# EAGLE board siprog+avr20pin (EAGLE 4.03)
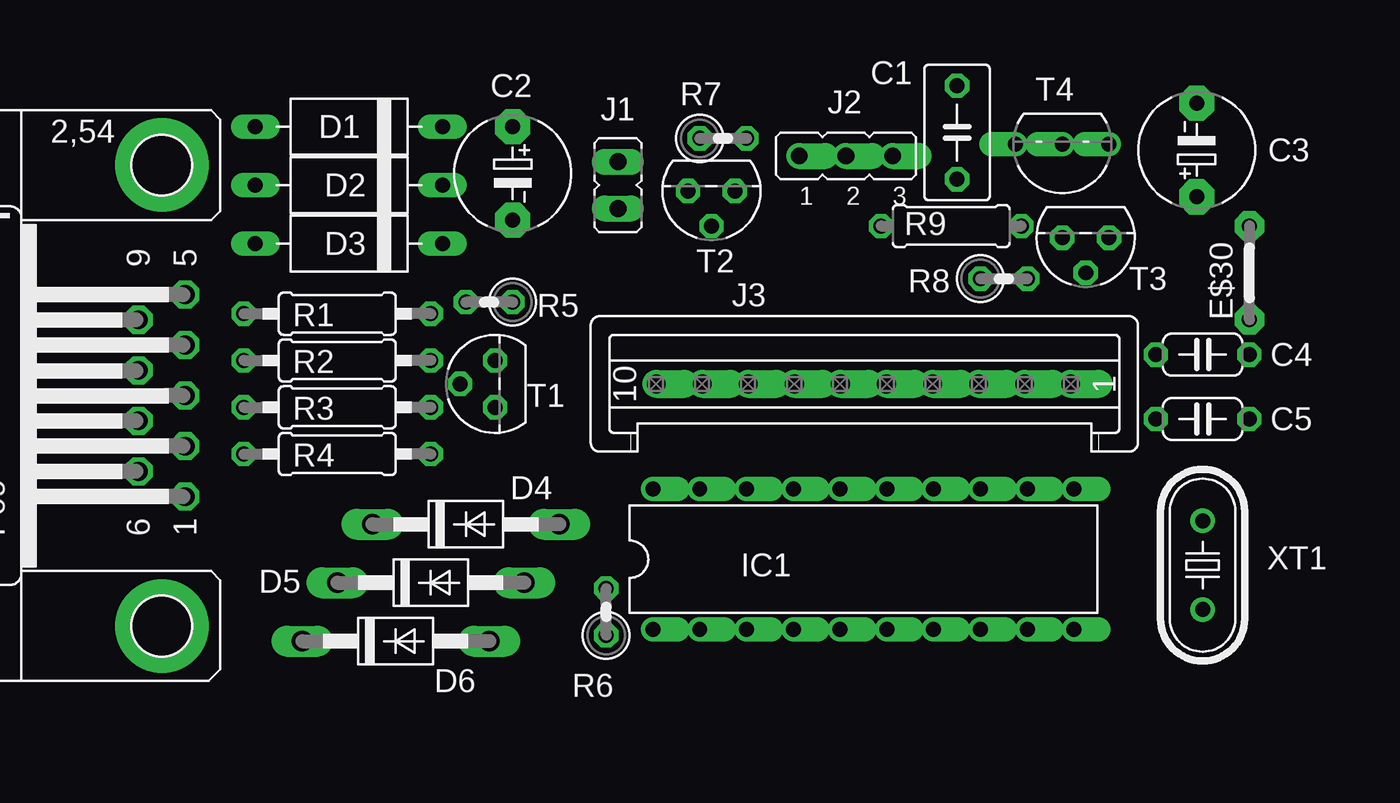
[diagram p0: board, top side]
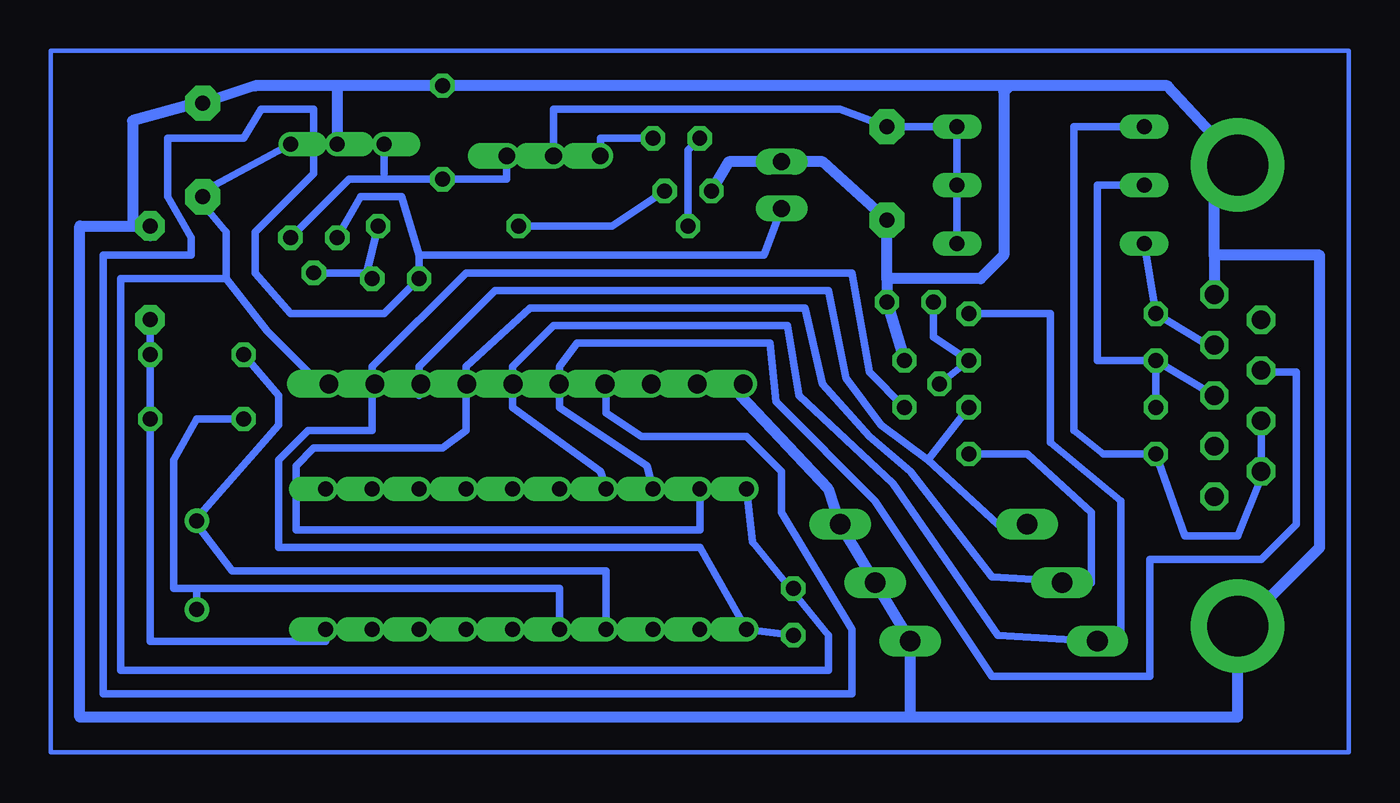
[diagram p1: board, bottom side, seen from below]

No outline drawn. Coordinates in mm, seen from the top.
Copper layers used: Bottom

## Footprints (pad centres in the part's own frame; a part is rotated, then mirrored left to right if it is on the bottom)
C050-035X075 = drill 0.813 octagon: 1 -2.54,0; 2 2.54,0
E5-6 = drill 0.813 pad 1.905 octagon: + -2.54,0; - 2.54,0
C050-024X044 = drill 0.813 octagon: 1 -2.54,0; 2 2.54,0
F09HP = drill 1.016 octagon: 1 -5.486,-1.27; 2 -2.743,-1.27; 3 0,-1.27; 4 2.743,-1.27; 5 5.486,-1.27; 6 -4.115,1.27; 7 -1.372,1.27; 8 1.372,1.27; 9 4.115,1.27 | drill 3.302 pad 5.08 round: G1 -12.522,0; G2 12.522,0
D-10 = drill 0.813 long: A 5.08,0; C -5.08,0
DO41-10 = drill 1.118 long: A 5.08,0; C -5.08,0
05 = drill 0.813 pad 1.6 octagon: 1 -2.54,0; 2 2.54,0
DIL-20 = drill 0.813 offset: 1 -11.43,-3.81; 2 -8.89,-3.81; 3 -6.35,-3.81; 4 -3.81,-3.81; 5 -1.27,-3.81; 6 1.27,-3.81; 7 3.81,-3.81; 8 6.35,-3.81; 9 8.89,-3.81; 10 11.43,-3.81; 11 11.43,3.81; 12 8.89,3.81; 13 6.35,3.81; 14 3.81,3.81; 15 1.27,3.81; 16 -1.27,3.81; 17 -3.81,3.81; 18 -6.35,3.81; 19 -8.89,3.81; 20 -11.43,3.81
JP1Y = drill 0.914 long: 1 0,-1.27; 2 0,1.27
JP2 = drill 0.914 offset: 1 -2.54,0; 2 0,0; 3 2.54,0
S10P = drill 1.016 offset: 1 11.25,0; 2 8.75,0; 3 6.25,0; 4 3.75,0; 5 1.25,0; 6 -1.25,0; 7 -3.75,0; 8 -6.25,0; 9 -8.75,0; 10 -11.25,0
0207/10 = drill 0.813 octagon: 1 -5.08,0; 2 5.08,0
0207/2V = drill 0.813 octagon: 1 -1.27,0; 2 1.27,0
0207/7 = drill 0.813 octagon: 1 -3.81,0; 2 3.81,0
TO92 = drill 0.813 octagon: 1 1.27,0; 2 0,1.905; 3 -1.27,0
TO92- = drill 0.813 offset: 1 2.54,-1.27; 2 0,-1.27; 3 -2.54,-1.27
HC49U-V = drill 0.813 round: 1 -2.413,0; 2 2.413,0

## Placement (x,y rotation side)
C1  [C050-035X075]  59.69,60.01 90 top
C2  [E5-6]  35.56,57.78 270 top
C3  [E5-6]  72.71,59.05 90 top
C4  [C050-024X044]  73.03,47.94 0 top
C5  [C050-024X044]  73.03,44.45 0 top
COM1  [F09HP]  16.51,45.72 90 top
D1  [D-10]  26.67,60.33 180 top
D2  [D-10]  26.67,57.15 180 top
D3  [D-10]  26.67,53.98 180 top
D4  [DO41-10]  33.02,38.73 0 top
D5  [DO41-10]  31.11,35.56 0 top
D6  [DO41-10]  29.21,32.38 0 top
E$30  [05]  75.56,52.39 90 top
IC1  [DIL-20]  54.61,36.83 0 top
J1  [JP1Y]  41.27,57.15 0 top
J2  [JP2]  53.66,58.74 0 top
J3  [S10P]  54.61,46.35 0 top
R1  [0207/10]  26.04,50.16 0 top
R2  [0207/10]  26.04,47.62 0 top
R3  [0207/10]  26.04,45.09 0 top
R4  [0207/10]  26.04,42.55 0 top
R5  [0207/2V]  34.29,50.8 180 top
R6  [0207/2V]  40.64,33.97 90 top
R7  [0207/2V]  46.99,59.69 0 top
R8  [0207/2V]  62.23,52.07 0 top
R9  [0207/7]  59.37,54.93 0 top
T1  [TO92]  34.61,46.35 90 top
T2  [TO92]  46.35,56.83 180 top
T3  [TO92]  66.67,54.29 180 top
T4  [TO92-]  65.41,58.1 180 top
XT1  [HC49U-V]  73.03,36.51 270 top

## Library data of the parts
C1-C5 R1-R9 = rcl
COM1 = con-subd
D1-D6 = diode
E$30 J1 J2 = jumper
IC1 = ic-package
J3 = con-amp-mt
T1-T3 = transistor-npn
T4 = transistor-pnp
XT1 = crystal

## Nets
S$1: IC1.18
S$2: D4.C
S$3: D1.A
S$4: D3.A
S$5: COM1.3 D2.A R3.1
S$6: IC1.19 R4.2
S$7: T4.1
S$8: R2.2 T1.2
S$9: R6.1 T1.3
S$10: C2.- C3.- D4.A D6.A T1.1 T2.1 T4.2
S$11: IC1.17
S$12: T2.3
S$13: C2.+ D1.C D2.C D3.C
S$14: R7.1 T2.2
S$15: J1.1 R8.1
S$16: R8.2 R9.2 T3.2
S$17: C4.2 IC1.10
S$20: T3.1
S$21: IC1.4
S$22: IC1.5
S$23: C3.+ T4.3
S$24: C4.1
S$25: C5.1
S$26: J1.2
S$28: J2.1 R7.2
S$31: C1.1 J2.3 T3.3

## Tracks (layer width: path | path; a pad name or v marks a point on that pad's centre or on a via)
S$1
  Bottom 0.406: 15.24,46.99 13.34,46.99 13.34,38.73 15.24,36.83 21.27,36.83 21.27,30.48 29.84,30.48 36.2,40.01 41.59,45.4 41.91,48.58 52.39,48.58 53.34,47.31 53.34,45.09 48.58,41.91 IC1.18
S$2
  Bottom 0.406: 33.34,42.23 35.88,44.13 37.78,46.67 38.73,51.44 56.83,51.44 60.96,47.31 60.96,45.72 | 33.34,42.23 29.53,38.73 D4.C | 33.34,42.23 31.11,45.09
S$3
  Bottom 0.406: D1.A 25.4,60.33 25.4,43.81 23.81,42.55 20.95,42.55 19.37,38.1 16.51,38.1 15.24,41.27
S$4
  Bottom 0.406: 17.78,48.26 20.95,50.16 D3.A
S$5
  Bottom 0.406: COM1.3 20.95,47.62 | R3.1 20.95,47.62 | 20.95,47.62 24.13,47.62 24.13,57.15 D2.A
S$6
  Bottom 0.406: IC1.19 45.72,38.42 67.63,38.42 67.63,41.91 66.67,42.86 59.69,42.86 58.42,43.81 58.42,47.31 54.93,50.48 40.01,50.48 39.05,46.35 36.51,43.5 34.29,41.59 29.84,35.88 24.45,35.56 24.45,39.37 27.94,42.55 R4.2
S$7
  Bottom 0.406: 62.87,57.78 T4.1
S$8
  Bottom 0.406: T1.2 R2.2 33.02,48.9 33.02,50.8
S$9
  Bottom 0.406: T1.3 36.51,46.99 37.47,52.39 58.42,52.39 63.5,47.31 63.5,43.81 66.99,43.81 68.58,42.23 68.58,37.47 45.72,37.47 43.18,33.02 R6.1
S$10
  Bottom 0.61: T1.1 35.56,50.8 35.56,52.07 | 35.56,52.07 30.48,52.07 29.21,53.34 29.21,62.23 28.89,62.55 | C3.- 69.85,62.55 65.41,62.55 | 65.41,62.55 T4.2 | 28.89,62.55 65.41,62.55 | 28.89,62.55 20.32,62.55 16.51,58.42 | 16.51,60.33 15.24,59.69 | 14.61,58.42 15.24,59.69 | 15.24,57.15 14.61,58.42 | 16.51,60.33 17.78,60.01 18.41,58.42 | 16.51,56.52 15.24,57.15 | 16.51,58.42 16.51,56.52 | 16.51,58.42 14.61,58.42 | 16.51,58.42 16.51,60.33 | 16.51,58.42 15.24,57.15 | 16.51,58.42 15.24,59.69 | 16.51,58.42 18.41,58.42 | 17.78,57.15 16.51,58.42 | 17.78,57.15 16.51,56.52 | 17.78,57.15 18.41,58.42 | 17.78,53.34 17.78,51.44 | 17.78,53.34 17.78,57.15 | 17.78,53.34 12.06,53.34 12.06,37.47 15.24,34.29 | 43.5,45.72 38.73,40.64 D4.A D6.A 34.29,28.26 16.51,28.26 16.51,31.43 | 16.51,34.92 17.78,34.29 | 15.24,34.29 16.51,34.92 | 14.61,33.02 15.24,34.29 | 18.41,33.02 17.78,34.29 | 17.78,31.75 18.41,33.02 | 15.24,31.75 14.61,33.02 | 16.51,33.02 15.24,34.29 | 16.51,33.02 17.78,31.75 | 16.51,33.02 16.51,34.92 | 16.51,33.02 17.78,34.29 | 16.51,33.02 18.41,33.02 | 16.51,33.02 14.61,33.02 | 16.51,33.02 15.24,31.75 | 16.51,31.43 16.51,33.02 | 16.51,31.43 15.24,31.75 | 16.51,31.43 17.78,31.75 | T2.1 44.13,58.42 39.05,58.42 C2.- 35.56,52.07
S$11
  Bottom 0.406: 51.12,40.64 IC1.17 51.12,41.59 55.88,45.09
S$12
  Bottom 0.406: T2.3 50.48,54.93 55.56,54.93
S$13
  Bottom 0.406: 53.66,59.05 53.66,61.28 38.1,61.28 C2.+ D1.C D2.C D3.C
S$14
  Bottom 0.406: T2.2 46.35,59.05 R7.1
S$15
  Bottom 0.406: J1.1 42.23,53.34 60.96,53.34 R8.1 62.87,50.16 67.94,50.16 69.85,52.39 69.85,54.61 66.67,57.78 66.67,61.28 69.53,61.28 70.48,59.69 74.61,59.69 74.61,56.52 73.34,54.29 73.34,53.34 78.11,53.34 78.11,29.53 37.47,29.53 37.47,33.02 41.27,39.37 41.27,41.59 43.18,43.5 48.9,43.5 50.8,44.77 50.8,46.04
S$16
  Bottom 0.406: R8.2 63.82,52.39 | R9.2 63.82,52.39 | 63.82,52.39 T3.2
S$17
  Bottom 0.406: IC1.10 66.04,32.38 75.56,32.38 C4.2 | 75.56,49.85 C4.2 | 75.56,49.53 C4.2
S$18
  Bottom 0.406: 72.71,61.91 73.03,61.59 | 75.56,54.93 75.56,54.29
  Bottom 0.61: 73.03,61.59 76.52,60.64 76.52,54.93 75.56,54.93 79.38,54.93 79.38,28.26 31.75,28.26
S$19
  Bottom 0.406: 31.11,50.16 26.67,50.16 26.67,43.18 22.86,40.01 22.86,32.38 24.13,32.38 29.53,32.7 35.24,40.96 40.32,45.72 40.96,49.53 53.66,49.53 55.88,47.31 55.88,45.09
S$20
  Bottom 0.406: T3.1 64.14,56.52 61.91,56.52 60.96,53.34
S$21
  Bottom 0.406: IC1.4 50.8,36.2 71.12,36.2 73.03,38.73
S$22
  Bottom 0.406: IC1.5 53.34,35.24 73.03,35.24 | 74.3,35.24 73.03,35.24 | 73.03,35.24 73.03,34.29
S$23
  Bottom 0.406: T4.3 72.07,57.15 C3.+ 73.03,56.52 71.44,54.61 71.44,52.07 | 66.04,46.04 69.22,49.21 71.44,52.07 | 71.44,52.07 77.15,52.07 77.15,30.8 38.73,30.8 38.73,32.7 42.86,37.78 43.18,40.64
S$24
  Bottom 0.406: 73.03,39.05 68.58,44.13 68.58,45.72 C4.1
S$25
  Bottom 0.406: 74.3,35.24 74.3,42.23 73.03,44.45 C5.1
S$27
  Bottom 0.254: 10.48,64.45 80.96,64.45 80.96,26.35 10.48,26.35 10.48,64.45
S$28
  Bottom 0.406: J2.1 51.12,59.69 R7.2
S$31
  Bottom 0.406: T3.3 64.77,57.47 C1.1 56.2,57.47 J2.3
S$33
  Bottom 0.406: 15.24,41.59 15.24,44.45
